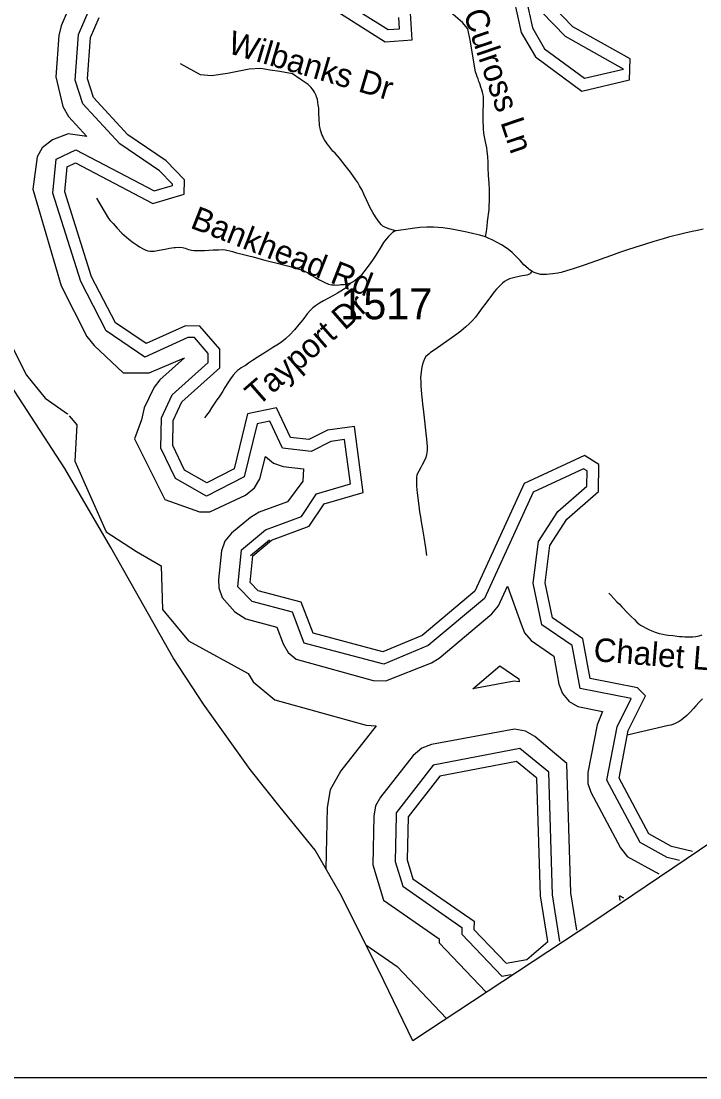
# Model space of a CAD drawing. Extents: x 1383679 to 1536984, y 460658 to 651027.
# Drawn here: x 1387456 to 1390201, y 477316 to 481592 of the extents above; entities that cross this region are included whole.
import ezdxf

# ---------------------------------------------------------------- set-up
doc = ezdxf.new("R2010")
doc.units = 0
for name, color, linetype in [('Exist Boundary Political StateLine', 7, 'Continuous'), ('Exist Hydrographic Bay Label', 7, 'Continuous'), ('Exist Hydrographic Buffer Line', 7, 'Continuous'), ('Exist Hydrographic Island Shore', 7, 'Continuous'), ('Exist Road Non-System Type 51', 7, 'Continuous'), ('Exist Road Non-System Type 51 Label', 7, 'Continuous'), ('Exist Road Secondary Type 51 Attributed', 7, 'Continuous'), ('Exist Road Secondary Type 51 Number Label', 7, 'Continuous'), ('Map Preparation Inset Cut Line', 7, 'Continuous')]:
    doc.layers.add(name, color=color, linetype=linetype)

msp = doc.modelspace()

# ---------------------------------------------------------------- linework, layer by layer
at = {"layer": 'Exist Boundary Political StateLine'}
for points in [[(1398984.8, 484134.2), (1398637.8, 483899.3), (1393778.1, 480652.5), (1392877.2, 480050.9), (1392272.5, 479643.3), (1390904.6, 478713.1), (1389768.3, 477946.4), (1389039.9, 477465.3), (1388903.7, 477748.1), (1388746.2, 478061.6), (1388645.7, 478237.7), (1388503.3, 478410.9), (1388382.4, 478563.4), (1388193.8, 478827.5), (1388071.7, 479016)], [(1388071.7, 479016), (1387818.8, 479461.5), (1387633.4, 479781.3), (1387259.2, 480355.5), (1387040.2, 480700.1), (1386912.2, 480890.9), (1386772.2, 481091.8), (1386609.2, 481331.4), (1386445.7, 481546.8), (1386289.6, 481746.2)]]:
    msp.add_lwpolyline(points, dxfattribs=at)
at = {"layer": 'Exist Hydrographic Bay Label'}
for points in [[(1388681.2, 481664.4), (1388928.2, 481508.4), (1389037.2, 481516.1), (1389031.2, 481624.5)], [(1389449.2, 481681.8), (1389479.1, 481546.5), (1389536.1, 481447), (1389724.1, 481308.7), (1389917.1, 481354), (1389919.1, 481439.3), (1389688.1, 481568.7), (1389606.1, 481652.4)], [(1388043.3, 481027.2), (1387887.2, 481132.1), (1387748.3, 481282.7), (1387724.2, 481358.6), (1387736.3, 481525.7), (1387771.3, 481607.1)], [(1390172.3, 478231.7), (1390086.1, 478252), (1389995.1, 478303.1), (1389875.1, 478528.7), (1389912.1, 478721.6), (1389982.1, 478861.4), (1389949.1, 478894.8), (1389758.2, 478931.5), (1389728.1, 479092.9), (1389605.1, 479177.4), (1389575.2, 479319.2), (1389594.1, 479469.8), (1389663.1, 479576.7), (1389791.1, 479689.1), (1389793.1, 479797.4), (1389735.1, 479834.6), (1389491.1, 479721.3), (1389291.2, 479285.5), (1389078.1, 479105.9), (1388919.2, 479040.2), (1388637.2, 479114.8), (1388589.2, 479240.5), (1388415.2, 479286.6), (1388382.2, 479320.1), (1388393.2, 479428.2), (1388469.3, 479492.3), (1388621.2, 479548.4), (1388681.2, 479639.1), (1388840.2, 479685.1), (1388804.2, 479951.7), (1388695.2, 479937.5), (1388620.2, 479899.7), (1388545.2, 479907.7), (1388489.2, 480027), (1388372.3, 480003.1), (1388317.2, 479781), (1388207.2, 479724.1), (1388117.2, 479775.2), (1388069.2, 479874.6), (1388071.3, 479976.3), (1388106.2, 480051.1), (1388259.2, 480189.2), (1388260.2, 480264.6), (1388179.2, 480358.2), (1388120.3, 480359.4), (1387961.3, 480287), (1387837.3, 480371.6), (1387741.2, 480557.3), (1387632.3, 480900.9), (1387642.3, 481002.4), (1387676.2, 481018.2), (1387989.2, 480854.4), (1388115.2, 480891.2), (1388116.3, 480950.2), (1388043.3, 481027.2)]]:
    msp.add_lwpolyline(points, dxfattribs=at)
at = {"layer": 'Exist Hydrographic Buffer Line'}
msp.add_line((1388460.6, 479492.3), (1388384.5, 479428.2), dxfattribs=at)
for points in [[(1388700.9, 481709.4), (1388940.6, 481558), (1388986, 481561.2), (1388983.5, 481606.9)], [(1389494.6, 481701.4), (1389525, 481564.3), (1389573.2, 481480.1), (1389734.9, 481361.1), (1389892.9, 481398.2), (1389658.3, 481529.7), (1389560.6, 481629.5)], [(1387658.6, 481667), (1387617.4, 481573.1), (1387608, 481534.4), (1387595.9, 481367.2), (1387625.2, 481246.3), (1387647.6, 481205.5), (1387721.7, 481125.1)], [(1388016.2, 480986.9), (1387855.4, 481094.9), (1387705.3, 481257.6), (1387675.1, 481352.8), (1387688.4, 481537.4), (1387731.7, 481638.2)], [(1387299.7, 481237.4), (1387242, 481137.4), (1387210.3, 480889.7), (1387348.7, 480414.5), (1387478.3, 480159.2), (1387553.1, 480066), (1387644.1, 480003.4), (1387643.5, 480001.9)], [(1387721.7, 481125.1), (1387646.7, 481136.3), (1387583.1, 481111.3), (1387541.6, 481079.6), (1387520.8, 481043.5), (1387504.1, 480912.6), (1387618.1, 480521), (1387722, 480316.4), (1387751.5, 480279.6), (1387868.7, 480169.4), (1387931.7, 480168.8), (1387973.4, 480168.8), (1388116.3, 480229.6), (1388017.1, 480140.1), (1387993.6, 480111), (1387953.9, 480027), (1387942.6, 479978.6), (1387914, 479901.5)], [(1389959.7, 478268.5), (1389825.4, 478521.2), (1389866.8, 478737), (1389924, 478851.3), (1389717.4, 478891), (1389685.1, 479064.9), (1389562.6, 479149.1), (1389527.1, 479317.2), (1389548.4, 479486.5), (1389626.9, 479608), (1389744, 479710.9), (1389745.2, 479771.7), (1389731.4, 479780.6), (1389526.9, 479685.7), (1389329.9, 479256), (1389103.1, 479064.9), (1388922.6, 478990.2), (1388601.5, 479075.1), (1388553.5, 479200.9), (1388390.5, 479244.1), (1388332.8, 479302.7), (1388347.9, 479452.1), (1388445, 479534), (1388590.2, 479587.5), (1388651.2, 479679.8), (1388787.7, 479719.3), (1388763.5, 479898.6), (1388709.4, 479891.5), (1388629, 479851), (1388513.6, 479863.4), (1388462.2, 479973), (1388411.1, 479962.6), (1388358.1, 479748.7), (1388206.2, 479670.2), (1388080.9, 479741.2), (1388021.6, 479864.2), (1388024, 479987.3), (1388067.3, 480079.9), (1388212, 480210.5), (1388212.5, 480247.2), (1388157.2, 480311.2), (1388130.1, 480311.7), (1387956.6, 480232.8), (1387800.7, 480339.1), (1387697.2, 480539.1), (1387584.1, 480895.9), (1387597.8, 481034.1), (1387677.5, 481071.1), (1387994.3, 480905.3), (1388068.4, 480926.9), (1388068.5, 480931.7), (1388016.2, 480986.9)], [(1387650.1, 479994.3), (1387681.3, 479958.2), (1387674, 479811.1), (1387800.4, 479525.1), (1387923.3, 479446), (1388022.8, 479387.6), (1388028.3, 479211.4), (1388132.9, 479084.8), (1388375.1, 478952.6)], [(1387914, 479901.5), (1388037.9, 479656.2), (1388139.3, 479619.7), (1388177.7, 479605.9), (1388219.3, 479605.9), (1388363.6, 479674.3), (1388400.5, 479703.8), (1388421.3, 479739.9), (1388444.5, 479830.7), (1388476.6, 479803.7), (1388515.7, 479789.5), (1388598.7, 479780.3), (1388598.7, 479780.3), (1388595.4, 479730.9), (1388534.1, 479647.3), (1388419, 479604.8), (1388383.3, 479584), (1388307.2, 479519.9), (1388280.5, 479488.2), (1388266.3, 479449), (1388254.2, 479332.2), (1388255.3, 479299.2), (1388269.6, 479260.1), (1388321, 479202.4), (1388365.5, 479173.8), (1388490.3, 479140.2), (1388516.4, 479071.9), (1388536.5, 479037.6), (1388568.5, 479010.8), (1388879.9, 478924.1), (1388931.4, 478921.9), (1389115.4, 478995), (1389146.8, 479014.1), (1389359.8, 479193.6), (1389386.5, 479225.4), (1389423.8, 479306)], [(1389423.8, 479306), (1389479.1, 479152.5), (1389492.5, 479117.3), (1389519.3, 479085.4), (1389610.6, 479022), (1389631.5, 478909.4), (1389645.6, 478871.4), (1389672.4, 478839.4), (1389708.5, 478818.6), (1389807.6, 478797.9), (1389785.7, 478744.1), (1389748.7, 478551.1), (1389748.3, 478507.7), (1389760.6, 478472.2), (1389880.5, 478246.6), (1389909.4, 478211)], [(1388375.1, 478952.6), (1388395.2, 478918.1), (1388481.7, 478845.8), (1388851.3, 478742.8), (1388892.1, 478741.1)], [(1389283.3, 478890.8), (1389392.7, 478983)], [(1389392.7, 478983), (1389468.6, 478930.3), (1389470.9, 478918.2)], [(1389470.9, 478918.2), (1389450.6, 478921.8), (1389283.3, 478890.8)], [(1388892.1, 478741.1), (1388748.6, 478557.9), (1388706.5, 478482), (1388693.3, 478410.4)], [(1389613.3, 478629.7), (1389533.5, 478697.3), (1389496, 478718.6), (1389451.4, 478726.5), (1389116.2, 478664.4), (1389076.3, 478649.5), (1389042.1, 478620.9), (1388909.3, 478451.4), (1388889.8, 478416.3), (1388882.3, 478375.6)], [(1389635.4, 477867.5), (1389605.6, 478057.1), (1389590, 478552.4), (1389473.3, 478648.1), (1389123.2, 478581), (1388972.8, 478388.9), (1388972.7, 478379.4)], [(1389703.6, 477913.8), (1389680, 478064.1), (1389663.5, 478588.5), (1389613.3, 478629.7)], [(1388693.3, 478410.4), (1388689.1, 478161.7)], [(1388882.3, 478375.6), (1388879, 478178.6), (1388922.2, 478035.7), (1389147.2, 477878.6), (1389146.8, 477862.8), (1389336.1, 477664.5)], [(1388972.7, 478379.4), (1388969.4, 478191.2), (1388999.5, 478091.7), (1389238.8, 477924.8), (1389238, 477897.9), (1389400.9, 477727.2)], [(1390118.9, 478195.5), (1390068.7, 478207.4), (1389959.7, 478268.5)], [(1390036.6, 478139.7), (1389909.4, 478211)], [(1389894.4, 478043.2), (1389876.6, 478053.1)], [(1389879.7, 478033.3), (1389876.6, 478053.1)], [(1388850.2, 477854.7), (1388976.7, 477766.4), (1389177, 477556.5)], [(1389400.9, 477727.2), (1389438.4, 477733.9)]]:
    msp.add_lwpolyline(points, dxfattribs=at)
at = {"layer": 'Exist Hydrographic Island Shore'}
msp.add_lwpolyline([(1389418.1, 477779.6), (1389501.1, 477794.3), (1389586.1, 477868.1), (1389557.1, 478052.6), (1389542.1, 478528.8), (1389460.1, 478596.1), (1389150.2, 478536.7), (1389021.1, 478371.8), (1389018.1, 478198), (1389041.1, 478121.9), (1389288.1, 477949.6), (1389287.2, 477916.8), (1389418.1, 477779.6)], dxfattribs=at)
at = {"layer": 'Exist Road Non-System Type 51'}
for points in [[(1389334.7, 480718.8), (1389338.2, 480740.4), (1389340.6, 480762), (1389343, 480781.8), (1389348.6, 480829.8), (1389349.6, 480847.1), (1389350.6, 480862.7), (1389350.6, 480886.4), (1389350.1, 480911.3), (1389348.6, 480934.7), (1389346.5, 480968.8), (1389345.5, 480998.1), (1389344.9, 481021), (1389343.9, 481042.9), (1389341.7, 481066), (1389339.8, 481078.9), (1389335, 481103.1), (1389330.9, 481123.7), (1389328.1, 481138.3), (1389326, 481157.8), (1389324.6, 481191.1), (1389325.5, 481227.6), (1389325.9, 481255.9), (1389326.2, 481272.3), (1389326.2, 481278.8), (1389325.7, 481285.4), (1389324.7, 481294.1), (1389322.3, 481305.1), (1389319.9, 481313.6), (1389316.1, 481325.2), (1389310.9, 481340), (1389307.9, 481348.2), (1389304.2, 481358.3), (1389301.2, 481367.1), (1389298.3, 481375.9), (1389293.9, 481387.4), (1389272.6, 481514.5), (1389262.8, 481560.4), (1389241.1, 481587.1), (1389156.4, 481659.8)], [(1388972, 480743.8), (1388962.2, 480746.2), (1388947.8, 480750.1), (1388936.9, 480753.7), (1388927.1, 480757.9), (1388919, 480762.7), (1388914, 480767.3), (1388905.1, 480777.7), (1388898.6, 480786.1), (1388889, 480800.4), (1388878.6, 480817.5), (1388867.5, 480837), (1388852.7, 480868.3), (1388842.7, 480891.2), (1388835, 480908.4), (1388825.3, 480925.8), (1388817.6, 480938.5), (1388809.9, 480950), (1388787.7, 480980.8), (1388766.5, 481008.3), (1388743.9, 481037), (1388725.7, 481057.8), (1388717.4, 481066), (1388709.1, 481077.1), (1388701.2, 481087.1), (1388694.1, 481095.6), (1388689.7, 481101.6), (1388684.8, 481109.1), (1388679.6, 481117.8), (1388675.8, 481125.9), (1388672.7, 481132.8), (1388669.4, 481142.1), (1388667.5, 481150.2), (1388665.4, 481159.1), (1388663.6, 481170), (1388662.6, 481180.1), (1388662, 481188.2), (1388661.3, 481200.9), (1388660.9, 481212.3), (1388660.4, 481225.2), (1388659.7, 481239.3), (1388658.2, 481253), (1388656.6, 481264.6), (1388654.7, 481274.9), (1388653.4, 481279.5), (1388651.2, 481286.3), (1388649.4, 481291.7), (1388646, 481298.9), (1388642.6, 481304.8), (1388638.6, 481311.1), (1388633.8, 481318), (1388629.4, 481323.2), (1388624.3, 481328.7), (1388617.4, 481334.9), (1388609.4, 481340.6), (1388585.1, 481357.8), (1388553.6, 481378.8), (1388502.3, 481388.3), (1388462.9, 481394.1), (1388425.5, 481399.8), (1388378.2, 481397.9), (1388291.5, 481380.7), (1388226.5, 481371.1), (1388181.2, 481375), (1388100.4, 481418.9)], [(1387760.9, 480875), (1387809.9, 480793.2), (1387816.1, 480785.4), (1387828.3, 480772.5), (1387844.9, 480754.4), (1387863.6, 480734.1), (1387892.1, 480709.2), (1387909.8, 480695.7), (1387924.9, 480685.9), (1387935.4, 480679.3), (1387950.2, 480671.1), (1387961, 480665.6), (1387968, 480663.1), (1387977.5, 480661), (1387984.9, 480660.7), (1387994.2, 480661.3), (1388015, 480665), (1388038.9, 480669.6), (1388056.1, 480672.9), (1388075.4, 480675.5), (1388079.9, 480676), (1388098, 480677.1), (1388109.4, 480675.9), (1388119.8, 480673.6), (1388126.4, 480670.9), (1388133.7, 480668.3), (1388139.5, 480666), (1388144.9, 480664.8), (1388154.1, 480664.1), (1388162.6, 480663.7), (1388175, 480663.7), (1388183.5, 480663.7), (1388198.1, 480664.1), (1388215.9, 480665.2), (1388232.9, 480666), (1388253.9, 480667), (1388270.7, 480667.5), (1388281.3, 480666.3), (1388288.3, 480664.9), (1388299.9, 480662.1), (1388310.4, 480659.3), (1388327.9, 480654.7), (1388339.2, 480651.9), (1388354.9, 480647.7), (1388376.7, 480641.7), (1388394, 480637.6), (1388417.2, 480631.4), (1388441.9, 480625.2), (1388463.1, 480619.8), (1388492.4, 480612.1), (1388517.5, 480605.6), (1388538.3, 480600.5), (1388558, 480594.8), (1388574.7, 480589.8), (1388592.8, 480583.7), (1388607.3, 480577.6), (1388619.2, 480571), (1388629.8, 480564.7), (1388647.3, 480554.1), (1388663.6, 480545.1), (1388684, 480534.4), (1388699.4, 480528.1), (1388711.7, 480525.3), (1388724.3, 480524.3), (1388735.8, 480524.1), (1388749.9, 480525.7), (1388762.2, 480526.7), (1388776.3, 480528.5), (1388791.7, 480533.4)], [(1389521.8, 480579.6), (1389516.9, 480572.4), (1389511.9, 480568.4), (1389501.6, 480564.5), (1389491.6, 480562.6), (1389476.2, 480559.5), (1389453.5, 480555.2), (1389442.6, 480552.2), (1389431.3, 480548.8), (1389420.5, 480544.4), (1389411.3, 480539.1), (1389402.8, 480531.9), (1389394.6, 480524.1), (1389379.3, 480508), (1389369.8, 480496), (1389358.1, 480481.4), (1389335.1, 480451.1), (1389321.4, 480432), (1389307.1, 480412.8), (1389293.5, 480394.7), (1389281.3, 480381), (1389267.7, 480366.9), (1389255.4, 480355.1), (1389246, 480346.9), (1389234.2, 480337), (1389217.9, 480325.1), (1389199.1, 480311.7), (1389176.9, 480296), (1389140, 480269.9), (1389111.1, 480249.8), (1389106.1, 480246.4), (1389098.3, 480239.3), (1389093.7, 480234.3), (1389088.2, 480225.9), (1389083.4, 480214.9), (1389079.7, 480203.3), (1389076.5, 480191.9), (1389073.7, 480172.3), (1389071.8, 480149.2), (1389072.2, 480132.7), (1389073, 480116.4), (1389076.1, 480082.5), (1389078.1, 480058), (1389080.1, 480041.4), (1389081.6, 480023.4), (1389096.2, 479900.3), (1389098.3, 479871.1), (1389097.9, 479854.6), (1389095.7, 479838.1), (1389092.9, 479826.3), (1389085.5, 479808.2), (1389078.7, 479796.3), (1389072.3, 479785.4), (1389064.3, 479771.4), (1389059.4, 479761.9), (1389056.7, 479754.6), (1389055.6, 479746.1), (1389055.2, 479734.2), (1389055.3, 479710.5), (1389057.7, 479682.7), (1389064.6, 479630.7), (1389068.1, 479606.7), (1389071.2, 479586.7), (1389074.6, 479565.9), (1389079.7, 479536.2), (1389084.7, 479504.5), (1389091.7, 479461.1), (1389096.1, 479429.6)], [(1388791.7, 480533.4), (1388776.4, 480519.8), (1388763.5, 480508.8), (1388749.9, 480499.4), (1388736.3, 480490.8), (1388717.4, 480480.3), (1388698.7, 480471.2), (1388678.7, 480460.3), (1388663.4, 480451.2), (1388647.3, 480440.5), (1388636.4, 480432), (1388626, 480422.5), (1388612.8, 480407.4), (1388594.9, 480383), (1388579.2, 480364), (1388562.2, 480343), (1388541, 480320.8), (1388529.9, 480310.1), (1388525.3, 480306.2), (1388515.9, 480298.2), (1388505.3, 480290.1), (1388490.4, 480280.8), (1388474.5, 480270.8), (1388457.8, 480260), (1388432.5, 480244.5), (1388410.7, 480230.6), (1388392.2, 480218.5), (1388376.4, 480208.1), (1388363.1, 480199.2), (1388355.6, 480194.6), (1388346.7, 480188.7), (1388339, 480183.4), (1388331.6, 480178), (1388324.5, 480171.2), (1388313.7, 480160), (1388302.5, 480145.1), (1388291.7, 480127.9), (1388280.7, 480109.3), (1388271.5, 480094.9), (1388259.6, 480076.2), (1388245.3, 480055), (1388234.5, 480038.8), (1388226.7, 480027), (1388216.1, 480011.4), (1388206.2, 479998), (1388198.4, 479986.6)], [(1389833.7, 479277.5), (1389841.4, 479269.4), (1389853.9, 479255.8), (1389866.2, 479242.7), (1389875.8, 479232.3), (1389885.8, 479222.3), (1389909.7, 479197), (1389925.1, 479181.9), (1389936.7, 479170.2), (1389947.1, 479159.8), (1389955.2, 479152.9), (1389961.9, 479147.7), (1389971.8, 479142.1), (1389981.5, 479136.7), (1389995, 479130.5), (1390006.6, 479125.5), (1390021.1, 479119.7), (1390037.3, 479114.7), (1390051.8, 479111.2), (1390064.4, 479109.3), (1390075, 479107.6), (1390092.4, 479105.5), (1390118.8, 479102.3), (1390130.3, 479101.6), (1390140.3, 479101.2), (1390150.7, 479100.8), (1390158.5, 479100.8), (1390173.1, 479101.2), (1390185.5, 479102), (1390199, 479104.7), (1390210.9, 479108.2)], [(1390211.8, 478849.1), (1390198.9, 478836.2), (1390185.5, 478821.6), (1390175.5, 478810), (1390162.6, 478795.7), (1390148.8, 478782.6), (1390134.1, 478769.9), (1390125.3, 478763), (1390117.9, 478758.3), (1390109.4, 478753.7), (1390101, 478749.8), (1390092.5, 478746.4), (1390083.6, 478743.7), (1390075, 478741.6), (1389907.4, 478702.1)]]:
    msp.add_lwpolyline(points, dxfattribs=at)
at = {"layer": 'Exist Road Secondary Type 51 Attributed'}
msp.add_lwpolyline([(1390215, 480750.4), (1390191.5, 480745.4), (1390170.5, 480741), (1390140, 480733.5), (1390075, 480717.4), (1390052.6, 480711.4), (1390015.8, 480700.1), (1389976.9, 480688.3), (1389938.5, 480676.1), (1389908.6, 480666.2), (1389876.7, 480655.4), (1389844.7, 480644.1), (1389816.5, 480634), (1389783.5, 480622.1), (1389734.1, 480604.8), (1389689.6, 480589.9), (1389661.5, 480581.3), (1389640.2, 480575.3), (1389627, 480572.4), (1389607.3, 480569.4), (1389593, 480567.9), (1389580.8, 480567), (1389566.5, 480566.5), (1389556.4, 480567.3), (1389542.9, 480570.3), (1389531.4, 480574.3), (1389521.8, 480579.6), (1389511.3, 480586.5), (1389507.8, 480589.6), (1389498.2, 480598.5), (1389490.1, 480606.3), (1389475, 480623.1), (1389461.3, 480637.2), (1389441.8, 480656.2), (1389427.4, 480668.2), (1389414.1, 480677), (1389399.6, 480686.3), (1389381.4, 480696.7), (1389361.8, 480706.5), (1389348, 480712.9), (1389334.7, 480718.8), (1389311.2, 480725.6), (1389287.1, 480731.5), (1389258.6, 480737.9), (1389212.2, 480747.2), (1389190.7, 480751.1), (1389162.1, 480755.3), (1389124, 480757.9), (1389097.6, 480757.7), (1389068.9, 480756.3), (1389039.8, 480752.8), (1389003, 480747.8), (1388972, 480743.8), (1388965.4, 480740.3), (1388958.5, 480736.1), (1388949.6, 480728), (1388941.9, 480721), (1388932.1, 480709.3), (1388922.1, 480696.4), (1388908, 480673.6), (1388890.3, 480644.6), (1388877.9, 480624.9), (1388864.4, 480605.4), (1388842.8, 480577), (1388832.7, 480566), (1388826.4, 480559.3), (1388816.6, 480549.9), (1388806.7, 480541.9), (1388799.8, 480537.3), (1388791.7, 480533.4)], dxfattribs=at)
at = {"layer": 'Map Preparation Inset Cut Line'}
msp.add_lwpolyline([(1446195.4, 477316), (1383679.3, 477316), (1383679.3, 520758.2), (1458567.8, 520758.2), (1458567.8, 493672.2), (1446195.4, 493672.2), (1446195.4, 477316)], dxfattribs=at)

# ---------------------------------------------------------------- texts
at = {"layer": 'Exist Road Non-System Type 51 Label'}
for s, rotation, p in [('Culross Ln', 288.802, (1389243.6, 481624.1)), ('Wilbanks Dr', 343.5797, (1388287, 481464.2)), ('Bankhead Rd', 338.6142, (1388136, 480757.1)), ('Tayport Dr', 41.2734, (1388414.2, 480030.7)), ('Chalet Ln', 355.405, (1389769.1, 479002.7))]:
    msp.add_text(s, height=95, rotation=rotation, dxfattribs=at).set_placement(p)
at = {"layer": 'Exist Road Secondary Type 51 Number Label'}
msp.add_text('1517', height=125, dxfattribs=at).set_placement((1388747.2, 480385.6))

doc.saveas('drawing.dxf')
